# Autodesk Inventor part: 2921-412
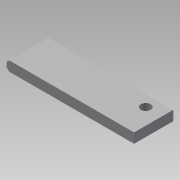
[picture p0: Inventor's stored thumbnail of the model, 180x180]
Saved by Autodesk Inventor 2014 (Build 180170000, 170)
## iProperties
Company: NHTSA/VRTC
Created: 2012-08
Part Number: 2921-412
Material: Steel, Mild
Document SubType Name: Modeling
Designer: Mike Vanvoorhis
Density: 7.86 g/cm^3
Mass: 818.915 g
Surface Area: 223.013 cm^2
Volume: 104.188 cm^3
Description: BUMPER BASE EXTENSION
Project: CHILD SIDE IMPACT SLED
Appearance: Steel
Stock Number: BAR 50.8 (2") X 12.7 (1/2") X 165.1 (6 1/2")
Author: Dave Walker
Title: Bumper Base Extension
Subject: Child Side Impact Sled
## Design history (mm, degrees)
sketch "Sketch1"
  geometry: L1 (0, 0)-(165.1, 0); L2 (165.1, 0)-(165.1, 12.7); L3 (165.1, 12.7)-(0, 12.7); L4 (0, 12.7)-(0, 0)
  constraints: 8 end point, 2 parallel, 1 horizontal, 1 perpendicular
  dimensions: "d0" = 165.1 distance of L3.end L2.end; "d1" = 12.7 distance of L2.end L1.end
extrude "Extrusion1" new body sketch "Sketch1" distance "d2" = 50.8; taper "d3" = 0 deg
sketch "Sketch3"
  geometry: L1 (0, 0)-(0, 50.8) reference; C1 r 6.35 at (-15.875, 36.1) reference; 1 further point
  constraints: 1 horizontal alignment
  dimensions: "d20" = 144.1196 distance from line of point (144.12, 36.1) L1
hole "Hole2" sketch "Sketch3" at (144.12, 36.1) diameter "d21" = 12.7; stored, may be unused: countersink angle "d25" = 82 deg, drill point angle "d27" = 118 deg; dims "d22" = 19.05, "d23" = 9.525, "d24" = 6.35, "d26" = 25.4
chamfer "Chamfer1" distance "d13" = 3.175; stored, may be unused: second distance "d14" = 3.175, angle "d15" = 45 deg
chamfer "Chamfer2" distance "d16" = 3.175; stored, may be unused: second distance "d17" = 3.175, angle "d18" = 45 deg
body "Solid1"
node "Reference2"
